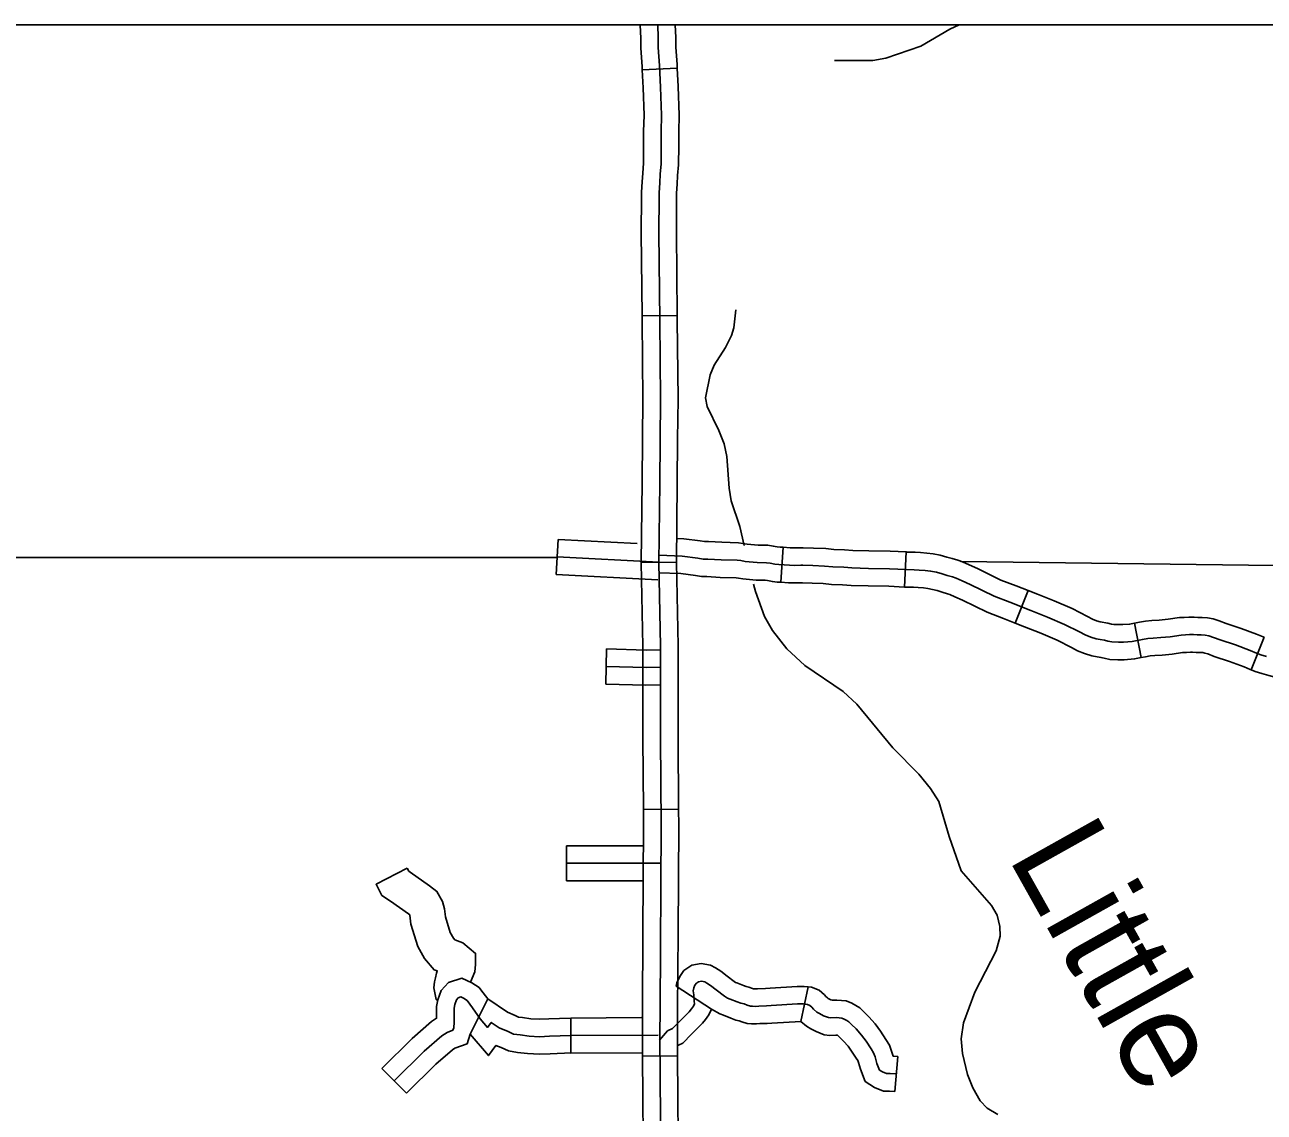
# Model space of a CAD drawing. Extents: x 1377389 to 1380723, y 1168351 to 1170484.
# Drawn here: x 1378723.7 to 1378829.8, y 1169486.3 to 1169579.4 of the extents above; entities that cross this region are included whole.
import ezdxf

# ---------------------------------------------------------------- set-up
doc = ezdxf.new("R2010")
doc.units = 0
doc.layers.add('B_Fill', color=7, linetype='Continuous')
doc.layers.add('B_Text', color=7, linetype='Continuous')

msp = doc.modelspace()

# ---------------------------------------------------------------- linework, layer by layer
at = {"layer": 'B_Fill'}
for p, q in [((1378776.52, 1169575.56), (1378779.52, 1169575.7)), ((1378776.52, 1169575.56), (1378776.52, 1169575.56)), ((1378779.5, 1169554.54), (1378776.5, 1169554.51)), ((1378769.16, 1169532.38), (1378769.32, 1169535.38)), ((1378788.39, 1169531.71), (1378788.59, 1169534.7)), ((1378798.96, 1169531.3), (1378799.11, 1169534.3)), ((1378779.44, 1169533.39), (1378776.44, 1169533.42)), ((1378808.44, 1169528.22), (1378809.55, 1169531.01)), ((1378819.23, 1169525.27), (1378818.64, 1169528.21)), ((1378828.64, 1169524.22), (1378829.75, 1169527)), ((1378773.39, 1169523), (1378773.47, 1169526)), ((1378776.63, 1169512.27), (1378779.63, 1169512.3)), ((1378770.03, 1169506.16), (1378770.03, 1169509.16)), ((1378779.43, 1169497.13), (1378782.44, 1169495.18)), ((1378790.71, 1169497.07), (1378790.1, 1169494.12)), ((1378761.79, 1169493.03), (1378763.29, 1169496.05)), ((1378770.41, 1169491.41), (1378770.4, 1169494.41)), ((1378776.54, 1169491.15), (1378779.54, 1169491.18)), ((1378798.38, 1169491.11), (1378798.13, 1169488.12)), ((1378756.35, 1169487.97), (1378754.23, 1169490.1))]:
    msp.add_line(p, q, dxfattribs=at)
for points in [[(1378776.52, 1169575.56), (1378776.51, 1169575.85), (1378776.39, 1169577.42), (1378776.39, 1169578.28), (1378776.35, 1169579.4), (1378776.35, 1169579.43)], [(1378778.16, 1169475.22), (1378778.03, 1169492.93), (1378778.04, 1169495.2), (1378778.14, 1169510.9), (1378778.08, 1169518.36), (1378778.08, 1169526.27), (1378777.94, 1169533.38), (1378778.01, 1169540.23), (1378778.08, 1169547.38), (1378778.01, 1169554.12), (1378777.94, 1169561.63), (1378777.96, 1169564.66), (1378777.96, 1169565.05), (1378778.01, 1169565.89), (1378778.06, 1169566.63), (1378778.13, 1169567.52), (1378778.14, 1169569.09), (1378778.14, 1169569.59), (1378778.14, 1169570.26), (1378778.17, 1169571.69), (1378778.09, 1169574.09), (1378778, 1169575.93), (1378777.89, 1169577.47), (1378777.89, 1169578.31), (1378777.85, 1169579.43)], [(1378779.52, 1169575.7), (1378779.5, 1169576.02), (1378779.39, 1169577.52), (1378779.39, 1169578.33), (1378779.35, 1169579.43)], [(1378803.63, 1169579.43), (1378802.85, 1169579.06), (1378800.36, 1169577.59), (1378797.38, 1169576.58), (1378796.25, 1169576.37), (1378792.98, 1169576.36)], [(1378776.46, 1169565.1), (1378776.51, 1169565.99), (1378776.56, 1169566.74), (1378776.63, 1169567.58), (1378776.64, 1169569.1), (1378776.64, 1169569.59), (1378776.64, 1169570.28), (1378776.67, 1169571.68), (1378776.59, 1169574.03), (1378776.52, 1169575.56)], [(1378779.52, 1169575.7), (1378779.59, 1169574.15), (1378779.67, 1169571.7), (1378779.64, 1169570.25), (1378779.64, 1169569.59), (1378779.64, 1169569.08), (1378779.63, 1169567.45), (1378779.55, 1169566.52), (1378779.5, 1169565.79), (1378779.46, 1169565.01)], [(1378776.5, 1169554.51), (1378776.44, 1169561.63), (1378776.46, 1169564.66), (1378776.46, 1169565.1)], [(1378779.46, 1169565.01), (1378779.46, 1169564.65), (1378779.44, 1169561.63), (1378779.5, 1169554.54)], [(1378776.54, 1169543.98), (1378776.58, 1169547.38), (1378776.51, 1169554.11), (1378776.5, 1169554.51)], [(1378779.54, 1169543.95), (1378779.58, 1169547.38), (1378779.51, 1169554.13), (1378779.5, 1169554.54)], [(1378784.54, 1169555.03), (1378784.36, 1169553.49), (1378784.16, 1169552.82), (1378783.65, 1169551.81), (1378782.66, 1169550.28), (1378782.33, 1169549.47), (1378781.92, 1169547.49), (1378782.07, 1169546.74), (1378783.08, 1169544.7), (1378783.53, 1169543.57), (1378783.75, 1169542.48), (1378783.96, 1169539.76), (1378784.13, 1169538.68), (1378784.86, 1169536.48), (1378785.25, 1169534.86)], [(1378776.44, 1169533.42), (1378776.51, 1169540.24), (1378776.54, 1169543.98)], [(1378779.44, 1169533.39), (1378779.51, 1169540.21), (1378779.54, 1169543.95)], [(1378769.32, 1169535.38), (1378776.08, 1169535.02)], [(1378779.46, 1169535.46), (1378780.07, 1169535.44), (1378781.47, 1169535.25), (1378781.85, 1169535.2), (1378782.19, 1169535.19), (1378783.32, 1169535.13), (1378784.75, 1169535.08), (1378785.14, 1169535.04), (1378785.51, 1169534.98), (1378786.44, 1169534.89), (1378787.27, 1169534.87), (1378787.73, 1169534.81), (1378788.08, 1169534.74), (1378788.32, 1169534.72), (1378788.59, 1169534.7)], [(1378777.97, 1169534.02), (1378779.94, 1169533.94), (1378781.27, 1169533.76), (1378781.72, 1169533.7), (1378782.12, 1169533.69), (1378783.26, 1169533.63), (1378784.65, 1169533.59), (1378784.95, 1169533.56), (1378785.32, 1169533.5), (1378786.35, 1169533.39), (1378787.16, 1169533.38), (1378787.48, 1169533.33), (1378787.87, 1169533.26), (1378788.2, 1169533.23), (1378789.11, 1169533.17), (1378789.57, 1169533.15), (1378790.08, 1169533.17), (1378790.26, 1169533.17), (1378791.11, 1169533.14), (1378792.11, 1169533.09), (1378792.83, 1169533.02), (1378793.76, 1169532.99), (1378794.47, 1169532.93), (1378795.88, 1169532.9), (1378797.68, 1169532.87), (1378799.12, 1169532.79), (1378799.8, 1169532.78), (1378800.22, 1169532.75), (1378800.73, 1169532.72), (1378801.19, 1169532.66), (1378801.7, 1169532.57), (1378802.18, 1169532.43), (1378802.61, 1169532.3), (1378803.07, 1169532.17), (1378803.39, 1169532.06), (1378803.89, 1169531.84), (1378804.58, 1169531.52), (1378806.63, 1169530.52), (1378807.99, 1169530.01), (1378809.79, 1169529.3), (1378811.21, 1169528.73), (1378812.67, 1169528.1), (1378813.94, 1169527.46), (1378814.42, 1169527.2), (1378814.9, 1169527.01), (1378815.36, 1169526.86), (1378815.72, 1169526.8), (1378816.08, 1169526.74), (1378816.38, 1169526.67), (1378816.71, 1169526.61), (1378817.27, 1169526.58), (1378817.71, 1169526.58), (1378818.44, 1169526.64), (1378819.33, 1169526.82), (1378819.8, 1169526.89), (1378820.26, 1169526.93), (1378820.89, 1169526.98), (1378821.69, 1169527.05), (1378822.63, 1169527.19), (1378823.01, 1169527.2), (1378823.36, 1169527.23), (1378823.69, 1169527.23), (1378824.01, 1169527.2), (1378824.36, 1169527.2), (1378824.69, 1169527.17), (1378825.02, 1169527.11), (1378825.41, 1169526.99), (1378825.99, 1169526.77), (1378827.28, 1169526.34), (1378828.56, 1169525.86), (1378829.1, 1169525.65), (1378829.47, 1169525.5), (1378829.96, 1169525.35)], [(1378788.59, 1169534.7), (1378789.19, 1169534.67), (1378789.58, 1169534.65), (1378790.06, 1169534.67), (1378790.29, 1169534.67), (1378791.17, 1169534.64), (1378792.22, 1169534.59), (1378792.93, 1169534.51), (1378793.84, 1169534.49), (1378794.55, 1169534.43), (1378795.9, 1169534.4), (1378797.73, 1169534.37), (1378799.11, 1169534.3)], [(1378799.11, 1169534.3), (1378799.17, 1169534.29), (1378799.87, 1169534.28), (1378800.32, 1169534.25), (1378800.87, 1169534.21), (1378801.42, 1169534.14), (1378802.03, 1169534.03), (1378802.6, 1169533.87), (1378803.04, 1169533.74), (1378803.52, 1169533.6), (1378803.93, 1169533.46), (1378804.51, 1169533.2), (1378805.22, 1169532.88), (1378807.22, 1169531.9), (1378808.52, 1169531.41), (1378809.55, 1169531.01)], [(1378769.28, 1169533.83), (1378672.17, 1169533.82)], [(1378769.24, 1169533.88), (1378777.94, 1169533.42)], [(1378776.44, 1169533.42), (1378776.44, 1169533.38), (1378776.58, 1169526.25), (1378776.58, 1169522.84)], [(1378779.58, 1169522.84), (1378779.58, 1169526.28), (1378779.44, 1169533.39), (1378779.44, 1169533.39)], [(1378873.17, 1169532.61), (1378803.78, 1169533.5)], [(1378769.16, 1169532.38), (1378777.86, 1169531.92)], [(1378777.92, 1169532.52), (1378779.82, 1169532.45), (1378781.07, 1169532.28), (1378781.59, 1169532.21), (1378782.06, 1169532.19), (1378783.2, 1169532.13), (1378784.55, 1169532.09), (1378784.75, 1169532.07), (1378785.12, 1169532.01), (1378786.26, 1169531.89), (1378787.04, 1169531.88), (1378787.24, 1169531.85), (1378787.66, 1169531.77), (1378788.08, 1169531.73), (1378788.39, 1169531.71)], [(1378786.04, 1169531.55), (1378786.2, 1169530.91), (1378786.97, 1169528.79), (1378787.67, 1169527.57), (1378788.89, 1169526), (1378790.43, 1169524.58), (1378793.72, 1169522.37), (1378794.89, 1169521.28), (1378797.97, 1169517.53), (1378800.19, 1169515.29), (1378801.19, 1169514.05), (1378801.9, 1169512.95), (1378802.78, 1169509.95), (1378803.82, 1169507.02), (1378806.4, 1169504.03), (1378806.89, 1169503.2), (1378807.13, 1169502.24), (1378807.14, 1169501.42), (1378806.8, 1169500.15), (1378804.98, 1169496.62), (1378804, 1169493.99), (1378803.8, 1169492.64), (1378803.94, 1169491.36), (1378804.37, 1169489.57), (1378804.8, 1169488.42), (1378805.45, 1169487.32), (1378806.03, 1169486.69), (1378806.94, 1169486.14)], [(1378788.39, 1169531.71), (1378789.04, 1169531.67), (1378789.57, 1169531.65), (1378790.1, 1169531.67), (1378790.24, 1169531.67), (1378791.05, 1169531.64), (1378792, 1169531.6), (1378792.73, 1169531.52), (1378793.67, 1169531.49), (1378794.39, 1169531.43), (1378795.85, 1169531.4), (1378797.63, 1169531.37), (1378798.96, 1169531.3)], [(1378798.96, 1169531.3), (1378799.06, 1169531.29), (1378799.73, 1169531.28), (1378800.12, 1169531.25), (1378800.59, 1169531.22), (1378800.96, 1169531.18), (1378801.36, 1169531.1), (1378801.75, 1169531), (1378802.18, 1169530.86), (1378802.63, 1169530.73), (1378802.84, 1169530.66), (1378803.28, 1169530.47), (1378803.94, 1169530.17), (1378806.03, 1169529.14), (1378807.45, 1169528.61), (1378808.44, 1169528.22)], [(1378809.55, 1169531.01), (1378810.35, 1169530.69), (1378811.78, 1169530.11), (1378813.31, 1169529.46), (1378814.63, 1169528.79), (1378815.06, 1169528.56), (1378815.41, 1169528.42), (1378815.72, 1169528.32), (1378816.38, 1169528.21), (1378816.69, 1169528.13), (1378816.88, 1169528.1), (1378817.31, 1169528.08), (1378817.64, 1169528.08), (1378818.23, 1169528.12), (1378818.64, 1169528.21)], [(1378818.64, 1169528.21), (1378819.07, 1169528.29), (1378819.6, 1169528.38), (1378820.13, 1169528.43), (1378820.76, 1169528.47), (1378821.52, 1169528.54), (1378822.5, 1169528.68), (1378822.91, 1169528.7), (1378823.3, 1169528.73), (1378823.76, 1169528.73), (1378824.08, 1169528.7), (1378824.43, 1169528.7), (1378824.9, 1169528.66), (1378825.38, 1169528.57), (1378825.9, 1169528.41), (1378826.5, 1169528.18), (1378827.78, 1169527.75), (1378829.09, 1169527.26), (1378829.65, 1169527.04), (1378829.75, 1169527)], [(1378808.44, 1169528.22), (1378809.24, 1169527.9), (1378810.64, 1169527.34), (1378812.04, 1169526.74), (1378813.25, 1169526.13), (1378813.78, 1169525.84), (1378814.38, 1169525.6), (1378815.01, 1169525.4), (1378815.77, 1169525.27), (1378816.06, 1169525.2), (1378816.53, 1169525.11), (1378817.23, 1169525.08), (1378817.77, 1169525.08), (1378818.65, 1169525.15), (1378819.23, 1169525.27)], [(1378773.47, 1169526), (1378776.85, 1169525.91), (1378778.06, 1169525.93)], [(1378819.23, 1169525.27), (1378819.6, 1169525.34), (1378819.99, 1169525.4), (1378820.38, 1169525.44), (1378821.01, 1169525.48), (1378821.87, 1169525.56), (1378822.77, 1169525.69), (1378823.1, 1169525.71), (1378823.43, 1169525.73), (1378823.62, 1169525.73), (1378823.94, 1169525.7), (1378824.3, 1169525.7), (1378824.49, 1169525.69), (1378824.67, 1169525.65), (1378824.92, 1169525.58), (1378825.48, 1169525.36), (1378826.77, 1169524.92), (1378828.03, 1169524.46), (1378828.55, 1169524.25), (1378828.64, 1169524.22)], [(1378773.43, 1169524.5), (1378776.84, 1169524.41), (1378778.08, 1169524.43)], [(1378828.64, 1169524.22), (1378828.97, 1169524.08), (1378829.54, 1169523.91), (1378830.15, 1169523.73), (1378830.85, 1169523.53), (1378831.46, 1169523.34), (1378833.76, 1169522.56), (1378836.35, 1169521.82), (1378837.33, 1169521.59), (1378837.94, 1169521.39), (1378838.86, 1169521.11)], [(1378773.39, 1169523), (1378776.83, 1169522.91), (1378778.09, 1169522.93)], [(1378776.58, 1169522.84), (1378776.58, 1169518.36), (1378776.63, 1169512.27)], [(1378779.63, 1169512.3), (1378779.58, 1169518.37), (1378779.58, 1169522.84)], [(1378776.58, 1169501.73), (1378776.64, 1169510.9), (1378776.63, 1169512.27)], [(1378779.58, 1169501.71), (1378779.64, 1169510.91), (1378779.63, 1169512.3)], [(1378770.03, 1169509.16), (1378776.62, 1169509.16)], [(1378770.03, 1169507.66), (1378778.12, 1169507.66)], [(1378759, 1169495.88), (1378758.87, 1169496), (1378758.68, 1169496.98), (1378758.75, 1169497.51), (1378758.82, 1169497.86), (1378758.9, 1169498.26), (1378758.98, 1169498.44), (1378758.7, 1169498.54), (1378757.89, 1169499.51), (1378757.3, 1169500.53), (1378756.72, 1169502.44), (1378756.63, 1169503.2), (1378756.62, 1169503.24), (1378756.52, 1169503.32), (1378754.97, 1169504.42), (1378754.23, 1169504.91), (1378753.74, 1169505.86), (1378756.39, 1169507.25)], [(1378761.82, 1169497.48), (1378762.19, 1169498.35), (1378762.25, 1169499), (1378762.25, 1169499.94), (1378761.16, 1169500.85), (1378760.48, 1169501.1), (1378760.36, 1169501.24), (1378760.08, 1169501.73), (1378759.67, 1169503.06), (1378759.59, 1169503.75), (1378759.43, 1169504.39), (1378758.94, 1169505.24), (1378758.31, 1169505.73), (1378756.67, 1169506.89), (1378756.53, 1169506.98), (1378756.39, 1169507.25)], [(1378770.03, 1169506.16), (1378776.62, 1169506.16)], [(1378776.54, 1169491.15), (1378776.53, 1169492.93), (1378776.54, 1169495.21), (1378776.58, 1169501.73)], [(1378779.54, 1169491.18), (1378779.53, 1169492.94), (1378779.54, 1169495.19), (1378779.58, 1169501.71)], [(1378790.71, 1169497.07), (1378790.39, 1169497.11), (1378789.77, 1169497.11), (1378787.46, 1169496.97), (1378787.07, 1169496.95), (1378786.39, 1169496.92), (1378786.22, 1169496.91), (1378786.06, 1169496.91), (1378786.05, 1169496.91), (1378785.95, 1169496.94), (1378785.65, 1169497.05), (1378785.4, 1169497.11), (1378785.19, 1169497.19), (1378784.61, 1169497.41), (1378784.5, 1169497.46), (1378784.38, 1169497.53), (1378783.78, 1169497.98), (1378783.25, 1169498.42), (1378782.8, 1169498.7), (1378782.37, 1169498.94), (1378781.56, 1169499.07), (1378780.77, 1169498.92), (1378780.09, 1169498.49), (1378779.73, 1169497.97), (1378779.47, 1169497.42), (1378779.43, 1169497.13)], [(1378754.23, 1169490.1), (1378756.82, 1169492.67), (1378758.48, 1169494.1), (1378758.92, 1169494.39), (1378758.9, 1169495.39), (1378759.02, 1169495.98), (1378759.31, 1169496.76), (1378759.93, 1169497.46), (1378761.09, 1169497.81), (1378761.94, 1169497.43), (1378762.55, 1169497.03), (1378762.8, 1169496.7)], [(1378798.25, 1169489.62), (1378797.73, 1169489.66), (1378797.43, 1169489.66), (1378797.09, 1169489.79), (1378796.83, 1169489.96), (1378796.61, 1169490.53), (1378796.44, 1169491.09), (1378796.31, 1169491.42), (1378796.1, 1169491.77), (1378795.68, 1169492.43), (1378795.29, 1169492.95), (1378794.83, 1169493.47), (1378794.42, 1169493.86), (1378794.19, 1169494.09), (1378794.04, 1169494.19), (1378793.8, 1169494.32), (1378793.61, 1169494.4), (1378793.13, 1169494.44), (1378792.63, 1169494.42), (1378792.45, 1169494.44), (1378792.03, 1169494.61), (1378791.68, 1169494.79), (1378791.47, 1169494.92), (1378791.18, 1169495.17), (1378791.04, 1169495.33), (1378790.87, 1169495.48), (1378790.65, 1169495.57), (1378790.31, 1169495.61), (1378789.82, 1169495.61), (1378787.54, 1169495.47), (1378787.14, 1169495.45), (1378786.49, 1169495.42), (1378786.25, 1169495.4), (1378785.96, 1169495.41), (1378785.77, 1169495.43), (1378785.49, 1169495.51), (1378785.23, 1169495.61), (1378784.96, 1169495.67), (1378784.64, 1169495.79), (1378784.04, 1169496.02), (1378783.82, 1169496.12), (1378783.55, 1169496.27), (1378782.85, 1169496.81), (1378782.37, 1169497.2), (1378782.05, 1169497.4), (1378781.87, 1169497.5), (1378781.58, 1169497.55), (1378781.33, 1169497.5), (1378781.15, 1169497.39), (1378781.03, 1169497.22), (1378780.93, 1169496.99), (1378780.89, 1169496.74), (1378780.92, 1169496.4), (1378780.97, 1169495.85), (1378780.99, 1169495.63), (1378780.91, 1169495.43), (1378780.73, 1169495.2), (1378780.54, 1169494.95), (1378780.22, 1169494.62), (1378779.67, 1169494.09), (1378779.11, 1169493.51), (1378778.69, 1169493.32), (1378778, 1169492.51)], [(1378798.38, 1169491.11), (1378797.99, 1169491.15), (1378797.86, 1169491.57), (1378797.67, 1169492.08), (1378797.37, 1169492.57), (1378796.91, 1169493.28), (1378796.46, 1169493.9), (1378795.91, 1169494.51), (1378795.47, 1169494.93), (1378795.13, 1169495.27), (1378794.81, 1169495.47), (1378794.46, 1169495.67), (1378793.96, 1169495.88), (1378793.16, 1169495.94), (1378792.78, 1169495.93), (1378792.65, 1169495.98), (1378792.42, 1169496.09), (1378792.37, 1169496.13), (1378792.24, 1169496.24), (1378792.11, 1169496.39), (1378791.67, 1169496.78), (1378791.01, 1169497.04), (1378790.71, 1169497.07)], [(1378755.29, 1169489.04), (1378757.84, 1169491.56), (1378759.38, 1169492.89), (1378759.81, 1169493.17), (1378760.32, 1169493.36), (1378760.38, 1169493.56), (1378760.43, 1169494.05), (1378760.41, 1169495.25), (1378760.47, 1169495.57), (1378760.62, 1169495.98), (1378760.77, 1169496.15), (1378760.98, 1169496.21), (1378761.22, 1169496.11), (1378761.52, 1169495.91), (1378761.99, 1169495.29), (1378762.65, 1169494.33), (1378763.28, 1169493.6), (1378763.6, 1169494.03), (1378764.26, 1169493.58), (1378765.03, 1169493.26), (1378765.5, 1169493.04), (1378766.06, 1169492.96), (1378766.83, 1169492.85), (1378767.73, 1169492.81), (1378768.59, 1169492.85), (1378770.41, 1169492.91)], [(1378762.8, 1169496.7), (1378763.21, 1169496.17), (1378763.29, 1169496.05), (1378764.98, 1169494.91), (1378765.63, 1169494.63), (1378765.94, 1169494.49), (1378766.28, 1169494.44), (1378766.97, 1169494.35), (1378767.73, 1169494.31), (1378768.52, 1169494.35), (1378770.35, 1169494.41)], [(1378782.44, 1169495.18), (1378782.21, 1169494.67), (1378781.93, 1169494.29), (1378781.68, 1169493.97), (1378781.28, 1169493.56), (1378780.73, 1169493.03), (1378780, 1169492.27), (1378779.62, 1169492.09), (1378779.55, 1169492.07)], [(1378790.1, 1169494.12), (1378787.62, 1169493.97), (1378787.21, 1169493.95), (1378786.58, 1169493.93), (1378786.29, 1169493.9), (1378785.86, 1169493.92), (1378785.5, 1169493.95), (1378785.03, 1169494.08), (1378784.81, 1169494.16), (1378784.53, 1169494.22), (1378784.1, 1169494.39), (1378783.47, 1169494.64), (1378783.15, 1169494.78), (1378782.44, 1169495.18)], [(1378770.4, 1169494.41), (1378776.45, 1169494.44)], [(1378798.13, 1169488.12), (1378797.67, 1169488.16), (1378797.16, 1169488.16), (1378796.4, 1169488.45), (1378795.6, 1169488.98), (1378795.19, 1169490.04), (1378795.02, 1169490.61), (1378794.96, 1169490.77), (1378794.83, 1169490.97), (1378794.44, 1169491.57), (1378794.13, 1169492), (1378793.75, 1169492.43), (1378793.37, 1169492.79), (1378793.25, 1169492.91), (1378793.22, 1169492.93), (1378793.1, 1169492.94), (1378792.57, 1169492.92), (1378792.08, 1169492.97), (1378791.41, 1169493.25), (1378790.94, 1169493.48), (1378790.57, 1169493.72), (1378790.1, 1169494.12)], [(1378756.35, 1169487.97), (1378758.86, 1169490.46), (1378760.28, 1169491.69), (1378760.49, 1169491.82), (1378761.52, 1169492.21), (1378761.79, 1169493.03)], [(1378761.79, 1169493.03), (1378763.35, 1169491.2), (1378764, 1169492.06), (1378764.43, 1169491.88), (1378765.07, 1169491.59), (1378765.84, 1169491.47), (1378766.69, 1169491.36), (1378767.73, 1169491.31), (1378768.65, 1169491.35), (1378770.46, 1169491.42)], [(1378770.41, 1169492.91), (1378777.88, 1169492.94)], [(1378770.41, 1169491.41), (1378776.61, 1169491.44)], [(1378776.62, 1169480.59), (1378776.54, 1169491.15)], [(1378779.54, 1169491.18), (1378779.62, 1169480.62)]]:
    msp.add_lwpolyline(points, dxfattribs=at)
at = {"layer": 'B_Text'}
msp.add_lwpolyline([(1378340.61, 1169579.43), (1379848.03, 1169579.43), (1379848.03, 1168702.1), (1378340.61, 1168702.1)], close=True, dxfattribs=at)

# ---------------------------------------------------------------- texts
at = {"layer": 'B_Fill'}
msp.add_text('Little', height=8.448, rotation=299.256, dxfattribs=at).set_placement((1378807.74, 1169508.23))

doc.saveas('drawing.dxf')
